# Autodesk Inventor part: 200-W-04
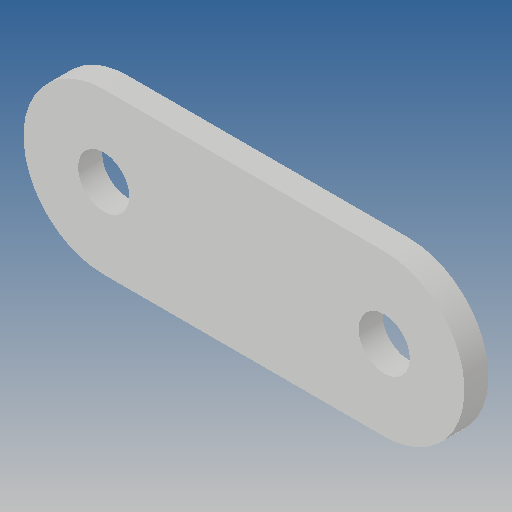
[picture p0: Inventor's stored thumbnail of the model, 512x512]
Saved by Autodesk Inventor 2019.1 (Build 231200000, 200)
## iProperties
Created: 2011-05
Part Number: 200-W-04
Material: Ogólny
Document SubType Name: Modeling
Designer: CADENGINEERING4
Density: 1 g/cm^3
Appearance: Domyślna
Author: CADENGINEERING4
Revision Number: ÈÎºÎ
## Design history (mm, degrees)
feature "À­Éì1"
node "Bryła1"
